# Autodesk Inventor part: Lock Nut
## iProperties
Shininess: 77.0
Length Units: 11269
Angle Units: 11279
Time Units: 11290
Mass Units: 11283
Length Display Precision: 3
Angle Display Precision: 2
Created: 2002-02
Part Number: Lock Nut
Document SubType Name: Modeling
Designer: ***
Stock Number: 02
Density: 0.0
Volumn: 0.0
Area: 0.0
PropertySet Name: Model Information
Control State: 0
Master: False
Checked Out: False
Author: ***
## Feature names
1. Extrusion1
2. Fillet1
3. Extrusion2
4. Hole1
